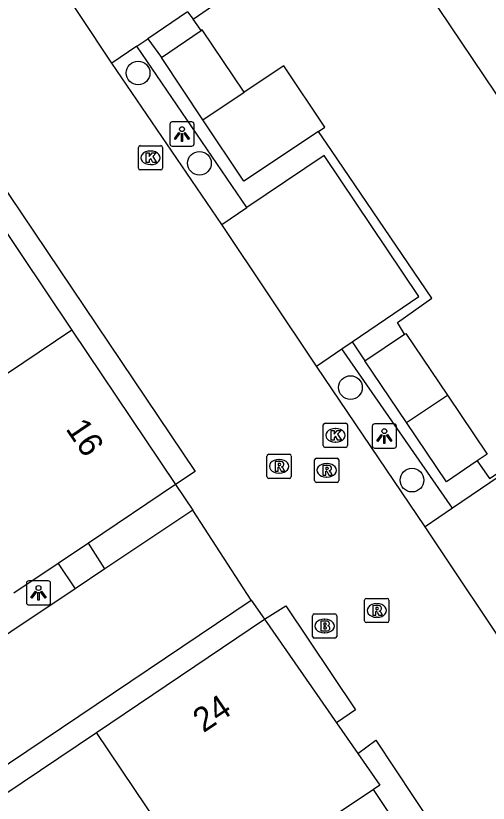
# Model space of a CAD drawing. Extents: x 158797 to 159887, y 384318 to 385255.
# Drawn here: x 159236.18 to 159255.68, y 384604.26 to 384636.77 of the extents above; entities that cross this region are included whole.
import ezdxf

# ---------------------------------------------------------------- set-up
doc = ezdxf.new("R2010")
doc.units = 0
for name, color, linetype in [('IMGEO_Boom', 7, 'Continuous'), ('IMGEO_Brandkraan', 7, 'Continuous'), ('IMGEO_Groenvoorziening', 7, 'Continuous'), ('IMGEO_Haag', 7, 'Continuous'), ('IMGEO_Kolk', 7, 'Continuous'), ('IMGEO_Lichtpunt', 7, 'Continuous'), ('IMGEO_Pand', 7, 'Continuous'), ('IMGEO_Pand_nummerreeks', 7, 'Continuous'), ('IMGEO_Parkeervlak_open', 7, 'Continuous'), ('IMGEO_Rijbaan_lokaal_open', 7, 'Continuous'), ('IMGEO_Rioolput', 7, 'Continuous'), ('IMGEO_Voetpad_open', 7, 'Continuous')]:
    doc.layers.add(name, color=color, linetype=linetype)

msp = doc.modelspace()

# ---------------------------------------------------------------- linework, layer by layer
at = {"layer": 'IMGEO_Boom'}
for centre in [(159241.232, 384634.41), (159243.764, 384630.684), (159249.995, 384621.423), (159252.537, 384617.603)]:
    msp.add_circle(centre, 0.489, dxfattribs=at)
at = {"layer": 'IMGEO_Brandkraan'}
for p, q in [((159248.43, 384611.152), (159248.43, 384612.004)), ((159248.505, 384612.078), (159249.357, 384612.078)), ((159248.918, 384611.858), (159248.943, 384611.858)), ((159249.431, 384612.004), (159249.431, 384611.152)), ((159248.941, 384611.298), (159248.916, 384611.298)), ((159249.357, 384611.078), (159248.505, 384611.078))]:
    msp.add_line(p, q, dxfattribs=at)
for points in [[(159248.43, 384611.152), (159248.43, 384612.004)], [(159248.505, 384612.078), (159249.357, 384612.078)], [(159249.431, 384612.004), (159249.431, 384611.152)], [(159248.778, 384611.778), (159248.778, 384611.378), (159248.991, 384611.378)], [(159249.009, 384611.778), (159248.778, 384611.778)], [(159248.957, 384611.697), (159248.903, 384611.697), (159248.903, 384611.621)], [(159248.903, 384611.621), (159248.956, 384611.621)], [(159248.965, 384611.545), (159248.903, 384611.545), (159248.903, 384611.464)], [(159248.903, 384611.464), (159248.965, 384611.464)], [(159249.357, 384611.078), (159248.505, 384611.078)]]:
    msp.add_lwpolyline(points, dxfattribs=at)
for centre, radius, start, end in [((159248.507, 384612.002), 0.0765, 91.552, 178.448), ((159248.507, 384612.002), 0.0765, 91.552, 178.448), ((159249.355, 384612.002), 0.0765, 1.552, 88.448), ((159249.355, 384612.002), 0.0765, 1.552, 88.448), ((159248.958, 384611.659), 0.0379, 267.8285, 90.9355), ((159248.966, 384611.504), 0.0404, 269.8759, 90.5077), ((159249.013, 384611.633), 0.145, 59.4692, 91.5367), ((159249.038, 384611.68), 0.0922, 285.5137, 58.1501), ((159249.043, 384611.488), 0.105, 301.3115, 78.989), ((159248.997, 384611.629), 0.251, 268.6676, 293.5347), ((159248.507, 384611.154), 0.0765, 181.552, 268.448), ((159248.507, 384611.154), 0.0765, 181.552, 268.448), ((159249.355, 384611.154), 0.0765, 271.552, 358.448), ((159249.355, 384611.154), 0.0765, 271.552, 358.448)]:
    msp.add_arc(centre, radius, start, end, dxfattribs=at)
for centre, major_axis, ratio, start_param, end_param in [((159248.917, 384611.578), (-0.387, 0.002), 0.722429, 4.712389, 7.853982), ((159248.942, 384611.578), (-0.39, 0.002), 0.717154, 1.570796, 4.712389)]:
    msp.add_ellipse(centre, major_axis=major_axis, ratio=ratio, start_param=start_param, end_param=end_param, dxfattribs=at)
at = {"layer": 'IMGEO_Groenvoorziening'}
for points in [[(159243.499, 384636.639), (159244.925, 384637.62), (159240.227, 384644.517)], [(159245.726, 384628.86), (159241.181, 384635.513)], [(159252.233, 384623.629), (159251.938, 384624.109), (159253.353, 384625.112), (159249.208, 384631.212), (159248.672, 384632.001)], [(159250.062, 384623.307), (159250.593, 384622.522)], [(159254.214, 384616.444), (159249.647, 384623.025)], [(159255.223, 384618.394), (159255.736, 384617.668), (159257.223, 384618.645), (159257.551, 384618.86), (159259.555, 384615.897)]]:
    msp.add_lwpolyline(points, dxfattribs=at)
at = {"layer": 'IMGEO_Haag'}
msp.add_lwpolyline([(159254.824, 384599.006), (159253.972, 384600.287), (159250.947, 384604.835)], dxfattribs=at)
at = {"layer": 'IMGEO_Kolk'}
for p, q in [((159241.244, 384630.485), (159241.244, 384631.337)), ((159241.319, 384631.411), (159242.171, 384631.411)), ((159242.245, 384631.337), (159242.245, 384630.485)), ((159241.732, 384631.191), (159241.757, 384631.191)), ((159242.171, 384630.411), (159241.319, 384630.411)), ((159241.755, 384630.631), (159241.73, 384630.631)), ((159248.951, 384619.953), (159249.803, 384619.953)), ((159248.876, 384619.027), (159248.876, 384619.879)), ((159249.364, 384619.733), (159249.389, 384619.733)), ((159249.877, 384619.879), (159249.877, 384619.027)), ((159249.387, 384619.173), (159249.362, 384619.173)), ((159249.803, 384618.953), (159248.951, 384618.953))]:
    msp.add_line(p, q, dxfattribs=at)
for points in [[(159241.244, 384630.485), (159241.244, 384631.337)], [(159241.319, 384631.411), (159242.171, 384631.411)], [(159242.245, 384631.337), (159242.245, 384630.485)], [(159241.565, 384631.111), (159241.688, 384631.111), (159241.688, 384630.96), (159241.818, 384631.111), (159241.982, 384631.111), (159241.836, 384630.96), (159241.989, 384630.711), (159241.837, 384630.711), (159241.752, 384630.875), (159241.688, 384630.808), (159241.688, 384630.711), (159241.565, 384630.711), (159241.565, 384631.111)], [(159242.171, 384630.411), (159241.319, 384630.411)], [(159248.951, 384619.953), (159249.803, 384619.953)], [(159248.876, 384619.027), (159248.876, 384619.879)], [(159249.197, 384619.653), (159249.32, 384619.653), (159249.32, 384619.502), (159249.45, 384619.653), (159249.614, 384619.653), (159249.468, 384619.502), (159249.621, 384619.253), (159249.469, 384619.253), (159249.384, 384619.417), (159249.32, 384619.35), (159249.32, 384619.253), (159249.197, 384619.253), (159249.197, 384619.653)], [(159249.877, 384619.879), (159249.877, 384619.027)], [(159249.803, 384618.953), (159248.951, 384618.953)]]:
    msp.add_lwpolyline(points, dxfattribs=at)
for centre, start, end in [((159241.321, 384631.335), 91.552, 178.448), ((159241.321, 384631.335), 91.552, 178.448), ((159242.169, 384631.335), 1.552, 88.448), ((159242.169, 384631.335), 1.552, 88.448), ((159241.321, 384630.487), 181.552, 268.448), ((159241.321, 384630.487), 181.552, 268.448), ((159242.169, 384630.487), 271.552, 358.448), ((159242.169, 384630.487), 271.552, 358.448), ((159248.953, 384619.877), 91.552, 178.448), ((159248.953, 384619.877), 91.552, 178.448), ((159249.801, 384619.877), 1.552, 88.448), ((159249.801, 384619.877), 1.552, 88.448), ((159248.953, 384619.029), 181.552, 268.448), ((159248.953, 384619.029), 181.552, 268.448), ((159249.801, 384619.029), 271.552, 358.448), ((159249.801, 384619.029), 271.552, 358.448)]:
    msp.add_arc(centre, 0.0765, start, end, dxfattribs=at)
for centre, major_axis, ratio, start_param, end_param in [((159241.731, 384630.911), (-0.387, 0.002), 0.722429, 4.712389, 7.853982), ((159241.756, 384630.911), (-0.39, 0.002), 0.717154, 1.570796, 4.712389), ((159249.363, 384619.453), (-0.387, 0.002), 0.722429, 4.712389, 7.853982), ((159249.388, 384619.453), (-0.39, 0.002), 0.717154, 1.570796, 4.712389)]:
    msp.add_ellipse(centre, major_axis=major_axis, ratio=ratio, start_param=start_param, end_param=end_param, dxfattribs=at)
at = {"layer": 'IMGEO_Lichtpunt'}
for p, q in [((159243.446, 384632.391), (159242.638, 384632.391)), ((159243.446, 384632.391), (159242.638, 384632.391)), ((159242.544, 384632.296), (159242.544, 384631.489)), ((159242.544, 384632.296), (159242.544, 384631.489)), ((159243.54, 384631.489), (159243.54, 384632.296)), ((159243.54, 384631.489), (159243.54, 384632.296)), ((159242.638, 384631.395), (159243.446, 384631.395)), ((159242.638, 384631.395), (159243.446, 384631.395)), ((159250.898, 384619.826), (159250.898, 384619.019)), ((159250.898, 384619.826), (159250.898, 384619.019)), ((159251.8, 384619.921), (159250.992, 384619.921)), ((159251.8, 384619.921), (159250.992, 384619.921)), ((159251.894, 384619.019), (159251.894, 384619.826)), ((159251.894, 384619.019), (159251.894, 384619.826)), ((159250.992, 384618.925), (159251.8, 384618.925)), ((159250.992, 384618.925), (159251.8, 384618.925)), ((159237.527, 384613.446), (159236.719, 384613.446)), ((159237.527, 384613.446), (159236.719, 384613.446)), ((159236.625, 384613.351), (159236.625, 384612.544)), ((159236.625, 384613.351), (159236.625, 384612.544)), ((159237.621, 384612.544), (159237.621, 384613.351)), ((159237.621, 384612.544), (159237.621, 384613.351)), ((159236.719, 384612.45), (159237.527, 384612.45)), ((159236.719, 384612.45), (159237.527, 384612.45))]:
    msp.add_line(p, q, dxfattribs=at)
for points in [[(159242.918, 384631.96), (159242.957, 384631.932), (159242.769, 384631.67), (159242.731, 384631.697), (159242.918, 384631.96)], [(159243.02, 384631.912), (159243.067, 384631.912), (159243.067, 384631.59), (159243.02, 384631.59), (159243.02, 384631.912)], [(159243.13, 384631.932), (159243.168, 384631.959), (159243.355, 384631.697), (159243.316, 384631.669), (159243.13, 384631.932)], [(159251.272, 384619.49), (159251.311, 384619.462), (159251.123, 384619.2), (159251.085, 384619.227), (159251.272, 384619.49)], [(159251.374, 384619.442), (159251.421, 384619.442), (159251.421, 384619.12), (159251.374, 384619.12), (159251.374, 384619.442)], [(159251.484, 384619.462), (159251.522, 384619.489), (159251.709, 384619.227), (159251.67, 384619.199), (159251.484, 384619.462)], [(159236.999, 384613.015), (159237.038, 384612.987), (159236.85, 384612.725), (159236.812, 384612.752), (159236.999, 384613.015)], [(159237.101, 384612.967), (159237.148, 384612.967), (159237.148, 384612.645), (159237.101, 384612.645), (159237.101, 384612.967)], [(159237.211, 384612.987), (159237.249, 384613.014), (159237.436, 384612.752), (159237.397, 384612.724), (159237.211, 384612.987)]]:
    msp.add_lwpolyline(points, dxfattribs=at)
for centre in [(159243.043, 384632.094), (159251.397, 384619.624), (159237.124, 384613.149)]:
    msp.add_circle(centre, 0.0994, dxfattribs=at)
for centre, start, end in [((159242.638, 384632.296), 90, 180), ((159242.638, 384632.296), 90, 180), ((159243.446, 384632.296), 0, 90), ((159243.446, 384632.296), 0, 90), ((159242.638, 384631.489), 180, 270), ((159242.638, 384631.489), 180, 270), ((159243.446, 384631.489), 270, 0), ((159243.446, 384631.489), 270, 360), ((159250.992, 384619.826), 90, 180), ((159250.992, 384619.826), 90, 180), ((159251.8, 384619.826), 0, 90), ((159251.8, 384619.826), 0, 90), ((159250.992, 384619.019), 180, 270), ((159250.992, 384619.019), 180, 270), ((159251.8, 384619.019), 270, 0), ((159251.8, 384619.019), 270, 360), ((159236.719, 384613.351), 90, 180), ((159236.719, 384613.351), 90, 180), ((159237.527, 384613.351), 0, 90), ((159237.527, 384613.351), 0, 90), ((159236.719, 384612.544), 180, 270), ((159236.719, 384612.544), 180, 270), ((159237.527, 384612.544), 270, 0), ((159237.527, 384612.544), 270, 360)]:
    msp.add_arc(centre, 0.0946, start, end, dxfattribs=at)
at = {"layer": 'IMGEO_Pand'}
for points in [[(159256.926, 384632.195), (159252.705, 384638.476)], [(159242.192, 384635.048), (159243.836, 384636.162)], [(159245.614, 384633.622), (159243.874, 384636.188), (159243.836, 384636.162)], [(159243.906, 384632.479), (159242.192, 384635.048)], [(159248.672, 384632.001), (159248.939, 384632.18), (159247.245, 384634.713), (159245.614, 384633.622)], [(159243.906, 384632.479), (159245.614, 384633.622)], [(159248.672, 384632.001), (159245.597, 384629.945), (159243.906, 384632.479)], [(159234.223, 384630.159), (159238.501, 384623.789)], [(159238.501, 384623.789), (159231.832, 384619.31)], [(159238.501, 384623.789), (159242.779, 384617.418)], [(159250.593, 384622.522), (159252.233, 384623.629)], [(159252.233, 384623.629), (159252.284, 384623.663), (159254.002, 384621.113)], [(159252.31, 384619.977), (159250.593, 384622.522)], [(159252.31, 384619.977), (159254.002, 384621.113)], [(159254.002, 384621.113), (159255.643, 384618.677), (159255.223, 384618.394)], [(159255.223, 384618.394), (159253.956, 384617.538), (159252.31, 384619.977)], [(159242.779, 384617.418), (159239.181, 384615.001)], [(159239.181, 384615.001), (159237.93, 384614.161)], [(159237.93, 384614.161), (159236.106, 384612.936)], [(159239.509, 384607.189), (159246.451, 384611.86)], [(159246.451, 384611.86), (159249.423, 384607.579)], [(159249.423, 384607.579), (159250.301, 384606.314)], [(159232.566, 384602.519), (159239.509, 384607.189)], [(159244.149, 384600.292), (159239.509, 384607.189)], [(159250.301, 384606.314), (159251.207, 384605.009), (159250.947, 384604.835)], [(159250.947, 384604.835), (159244.149, 384600.292)]]:
    msp.add_lwpolyline(points, dxfattribs=at)
at = {"layer": 'IMGEO_Parkeervlak_open'}
for points in [[(159241.181, 384635.513), (159241.632, 384635.819)], [(159241.181, 384635.513), (159240.152, 384634.812)], [(159250.062, 384623.307), (159252.817, 384625.181), (159248.916, 384631), (159245.726, 384628.86)], [(159244.685, 384628.162), (159245.726, 384628.86)], [(159249.647, 384623.025), (159250.062, 384623.307)], [(159248.597, 384622.31), (159249.647, 384623.025)], [(159259.212, 384615.668), (159257.291, 384618.543), (159254.214, 384616.444)], [(159254.214, 384616.444), (159253.077, 384615.668)]]:
    msp.add_lwpolyline(points, dxfattribs=at)
at = {"layer": 'IMGEO_Rijbaan_lokaal_open'}
for points in [[(159217.267, 384655.359), (159218.072, 384655.9), (159243.588, 384617.955), (159242.779, 384617.418)], [(159240.152, 384634.812), (159236.261, 384640.688)], [(159244.685, 384628.162), (159240.152, 384634.812)], [(159248.597, 384622.31), (159244.685, 384628.162)], [(159253.077, 384615.668), (159248.597, 384622.31)], [(159242.779, 384617.418), (159243.491, 384616.357)], [(159243.491, 384616.357), (159239.864, 384613.935)], [(159245.904, 384612.649), (159243.491, 384616.357)], [(159256.915, 384609.917), (159253.077, 384615.668)], [(159239.864, 384613.935), (159238.633, 384613.113)], [(159238.633, 384613.113), (159230.662, 384607.789)], [(159218.681, 384593.177), (159218.146, 384593.974), (159245.904, 384612.649)], [(159245.904, 384612.649), (159246.451, 384611.86)], [(159246.451, 384611.86), (159247.324, 384612.413), (159250.201, 384608.125), (159249.423, 384607.579)], [(159250.301, 384606.314), (159251.049, 384606.865), (159254.969, 384600.946)]]:
    msp.add_lwpolyline(points, dxfattribs=at)
at = {"layer": 'IMGEO_Rioolput'}
for p, q in [((159246.625, 384618.673), (159247.477, 384618.673)), ((159246.55, 384617.747), (159246.55, 384618.599)), ((159247.038, 384618.453), (159247.063, 384618.453)), ((159247.551, 384618.599), (159247.551, 384617.747)), ((159248.515, 384617.583), (159248.515, 384618.435)), ((159248.59, 384618.509), (159249.442, 384618.509)), ((159249.516, 384618.435), (159249.516, 384617.583)), ((159249.003, 384618.289), (159249.028, 384618.289)), ((159247.477, 384617.673), (159246.625, 384617.673)), ((159247.061, 384617.893), (159247.036, 384617.893)), ((159249.026, 384617.729), (159249.001, 384617.729)), ((159249.442, 384617.509), (159248.59, 384617.509)), ((159250.582, 384611.795), (159250.582, 384612.647)), ((159250.657, 384612.721), (159251.509, 384612.721)), ((159251.07, 384612.501), (159251.095, 384612.501)), ((159251.583, 384612.647), (159251.583, 384611.795)), ((159251.093, 384611.941), (159251.068, 384611.941)), ((159251.509, 384611.721), (159250.657, 384611.721))]:
    msp.add_line(p, q, dxfattribs=at)
for points in [[(159246.625, 384618.673), (159247.477, 384618.673)], [(159246.55, 384617.747), (159246.55, 384618.599)], [(159247.139, 384618.371), (159246.887, 384618.373), (159246.887, 384617.973)], [(159247.551, 384618.599), (159247.551, 384617.747)], [(159248.515, 384617.583), (159248.515, 384618.435)], [(159248.59, 384618.509), (159249.442, 384618.509)], [(159249.516, 384618.435), (159249.516, 384617.583)], [(159246.887, 384617.973), (159247.011, 384617.973), (159247.011, 384618.135), (159247.022, 384618.135)], [(159247.065, 384618.292), (159247.011, 384618.292), (159247.011, 384618.211)], [(159247.011, 384618.211), (159247.063, 384618.211)], [(159247.069, 384618.106), (159247.14, 384617.973), (159247.28, 384617.973), (159247.215, 384618.099)], [(159249.104, 384618.207), (159248.852, 384618.209), (159248.852, 384617.809)], [(159249.03, 384618.128), (159248.976, 384618.128), (159248.976, 384618.047)], [(159248.976, 384618.047), (159249.028, 384618.047)], [(159247.477, 384617.673), (159246.625, 384617.673)], [(159248.852, 384617.809), (159248.976, 384617.809), (159248.976, 384617.971), (159248.987, 384617.971)], [(159249.034, 384617.942), (159249.105, 384617.809), (159249.245, 384617.809), (159249.18, 384617.935)], [(159249.442, 384617.509), (159248.59, 384617.509)], [(159250.582, 384611.795), (159250.582, 384612.647)], [(159250.657, 384612.721), (159251.509, 384612.721)], [(159251.583, 384612.647), (159251.583, 384611.795)], [(159251.171, 384612.419), (159250.919, 384612.421), (159250.919, 384612.021)], [(159250.919, 384612.021), (159251.043, 384612.021), (159251.043, 384612.183), (159251.054, 384612.183)], [(159251.097, 384612.34), (159251.043, 384612.34), (159251.043, 384612.259)], [(159251.043, 384612.259), (159251.095, 384612.259)], [(159251.101, 384612.154), (159251.172, 384612.021), (159251.312, 384612.021), (159251.247, 384612.147)], [(159251.509, 384611.721), (159250.657, 384611.721)]]:
    msp.add_lwpolyline(points, dxfattribs=at)
for centre, radius, start, end in [((159246.627, 384618.597), 0.0765, 91.552, 178.448), ((159246.627, 384618.597), 0.0765, 91.552, 178.448), ((159247.475, 384618.597), 0.0765, 1.552, 88.448), ((159247.475, 384618.597), 0.0765, 1.552, 88.448), ((159247.138, 384618.261), 0.109, 350.3612, 89.416), ((159248.592, 384618.433), 0.0765, 91.552, 178.448), ((159248.592, 384618.433), 0.0765, 91.552, 178.448), ((159249.44, 384618.433), 0.0765, 1.552, 88.448), ((159249.44, 384618.433), 0.0765, 1.552, 88.448), ((159247.021, 384618.082), 0.0533, 26.0293, 88.6989), ((159247.047, 384618.4), 0.19, 274.7715, 282.9687), ((159247.071, 384618.196), 0.0964, 77.0061, 93.1865), ((159247.085, 384618.253), 0.0378, 276.6634, 79.6772), ((159247.136, 384618.261), 0.112, 277.5842, 350.9817), ((159247.12, 384618.046), 0.108, 29.5134, 73.7905), ((159249.012, 384618.236), 0.19, 274.7715, 282.9687), ((159249.036, 384618.032), 0.0964, 77.0061, 93.1865), ((159249.05, 384618.089), 0.0378, 276.6634, 79.6772), ((159249.103, 384618.097), 0.109, 350.3612, 89.416), ((159249.101, 384618.097), 0.112, 277.5842, 350.9817), ((159246.627, 384617.749), 0.0765, 181.552, 268.448), ((159246.627, 384617.749), 0.0765, 181.552, 268.448), ((159247.475, 384617.749), 0.0765, 271.552, 358.448), ((159247.475, 384617.749), 0.0765, 271.552, 358.448), ((159248.986, 384617.918), 0.0533, 26.0293, 88.6989), ((159249.085, 384617.882), 0.108, 29.5134, 73.7905), ((159248.592, 384617.585), 0.0765, 181.552, 268.448), ((159248.592, 384617.585), 0.0765, 181.552, 268.448), ((159249.44, 384617.585), 0.0765, 271.552, 358.448), ((159249.44, 384617.585), 0.0765, 271.552, 358.448), ((159250.659, 384612.645), 0.0765, 91.552, 178.448), ((159250.659, 384612.645), 0.0765, 91.552, 178.448), ((159251.507, 384612.645), 0.0765, 1.552, 88.448), ((159251.507, 384612.645), 0.0765, 1.552, 88.448), ((159251.053, 384612.13), 0.0533, 26.0293, 88.6989), ((159251.079, 384612.448), 0.19, 274.7715, 282.9687), ((159251.103, 384612.244), 0.0964, 77.0061, 93.1865), ((159251.117, 384612.301), 0.0378, 276.6634, 79.6772), ((159251.17, 384612.309), 0.109, 350.3612, 89.416), ((159251.168, 384612.309), 0.112, 277.5842, 350.9817), ((159251.152, 384612.094), 0.108, 29.5134, 73.7905), ((159250.659, 384611.797), 0.0765, 181.552, 268.448), ((159250.659, 384611.797), 0.0765, 181.552, 268.448), ((159251.507, 384611.797), 0.0765, 271.552, 358.448), ((159251.507, 384611.797), 0.0765, 271.552, 358.448)]:
    msp.add_arc(centre, radius, start, end, dxfattribs=at)
for centre, major_axis, ratio, start_param, end_param in [((159247.037, 384618.173), (-0.387, 0.002), 0.722429, 4.712389, 7.853982), ((159247.062, 384618.173), (-0.39, 0.002), 0.717154, 1.570796, 4.712389), ((159249.002, 384618.009), (-0.387, 0.002), 0.722429, 4.712389, 7.853982), ((159249.027, 384618.009), (-0.39, 0.002), 0.717154, 1.570796, 4.712389), ((159251.069, 384612.221), (-0.387, 0.002), 0.722429, 4.712389, 7.853982), ((159251.094, 384612.221), (-0.39, 0.002), 0.717154, 1.570796, 4.712389)]:
    msp.add_ellipse(centre, major_axis=major_axis, ratio=ratio, start_param=start_param, end_param=end_param, dxfattribs=at)
at = {"layer": 'IMGEO_Voetpad_open'}
for points in [[(159243.278, 384636.939), (159241.632, 384635.819)], [(159243.278, 384636.939), (159243.499, 384636.639)], [(159243.836, 384636.162), (159243.499, 384636.639)], [(159241.632, 384635.819), (159242.192, 384635.048)], [(159239.864, 384613.935), (159239.181, 384615.001)], [(159237.93, 384614.161), (159238.633, 384613.113)]]:
    msp.add_lwpolyline(points, dxfattribs=at)

# ---------------------------------------------------------------- texts
at = {"layer": 'IMGEO_Pand_nummerreeks'}
for s, rotation, p in [('16', 303.8845, (159238.22, 384619.722)), ('24', 33.9306, (159243.931, 384607.151))]:
    msp.add_text(s, height=1, rotation=rotation, dxfattribs=at).set_placement(p)

doc.saveas('drawing.dxf')
